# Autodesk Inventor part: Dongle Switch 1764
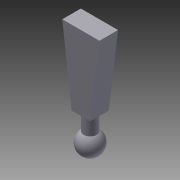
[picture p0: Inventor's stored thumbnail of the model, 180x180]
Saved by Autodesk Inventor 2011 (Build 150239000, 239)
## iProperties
Created: 2010-01
Part Number: Dongle Switch 1764
Document SubType Name: Modeling
Designer: jgehrig
Density: 1 g/cm^3
Author: jgehrig
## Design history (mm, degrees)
sketch "Sketch1"
  geometry: L1 (-6.921, 27.03)-(-1.841, 27.03); L2 (-3.111, 16.87)-(-5.651, 16.87); L3 (-6.921, 27.03)-(-5.651, 16.87); L4 (-3.111, 16.87)-(-1.841, 27.03); 1 further point
  constraints: 8 end point, 1 horizontal, 1 parallel
  dimensions: "d0" = 5.08 distance of L1.start L1.end; "d1" = 2.54 distance of L2.start L2.end; "d2" = 10.16 distance between parallel lines of L2 L1; "d3" = 1.27 horizontal distance of L1.start L2.end
extrude "Extrusion1" new body sketch "Sketch1" distance "d4" = 2.54; taper "d5" = 0 deg
workplane "Work Plane1"
sketch "Sketch2"
  geometry: L1 (-3.111, 16.87)-(-5.651, 16.87) reference; L2 (-4.381, 16.87)-(-4.381, 14.33); L3 (-3.492, 16.87)-(-3.492, 14.33); L4 (-4.381, 14.33)-(-3.492, 14.33); L5 (-4.381, 16.87)-(-3.492, 16.87); L6 (-4.381, 14.33)-(-4.381, 11.536); L7 (-4.381, 16.87)-(-3.492, 16.87); L8 (-3.492, 16.87)-(-4.381, 16.87); L9 (-4.381, 16.87)-(-3.492, 16.87); L10 (-3.492, 16.87)-(-3.492, 14.33); L11 (-3.492, 14.33)-(-4.381, 14.33); L12 (-4.381, 14.33)-(-4.381, 16.87); A1 r 1.587 centre (-4.381, 13.124) between (-4.381, 11.536) and (-4.381, 14.711); 1 further point
  constraints: 22 end point, 5 perpendicular, 3 parallel, 2 collinear, 2 point on circle, 2 point on line, 1 centre point, 1 horizontal, 1 midpoint
  dimensions: "d7" = 2.54 distance of L2.start L2.end; "d8" = 0.889 distance of L2.end L3.end; "d9" = 0 distance from line of L6 A1.centre; "d10" = 0.381 distance of A1.end L2.end; "d11" = 3.175 distance of L6.end A1.end
revolve "Revolution1" sketch "Sketch2" stored, may be unused: angle "d12" = 90 deg
body "Solid1"
other parameters: "d6" = 1.27
